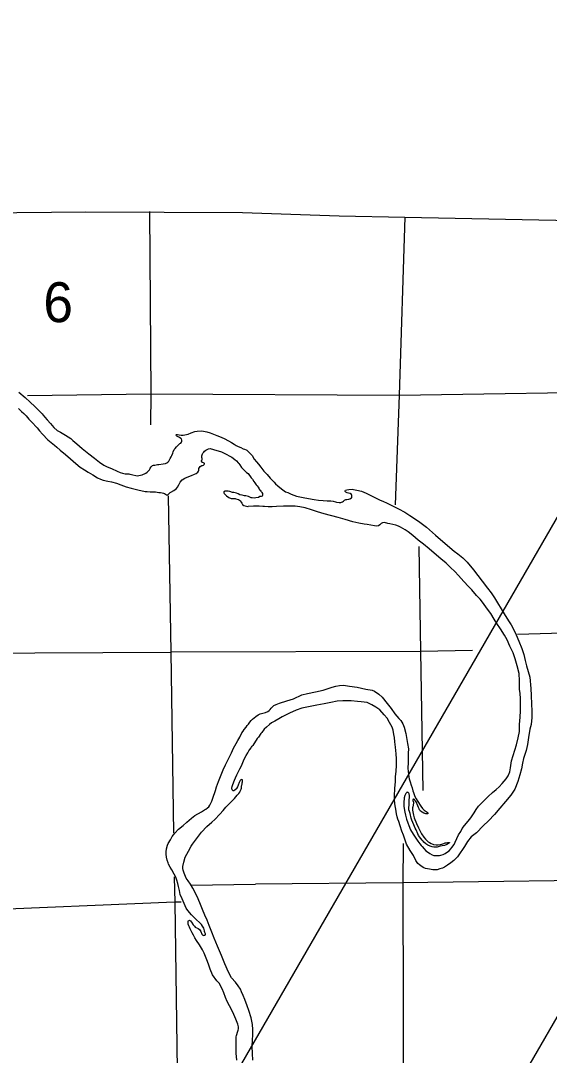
# Model space of a CAD drawing. Extents: x 369523 to 838377, y 495025 to 936819.
# Drawn here: x 640816 to 652011, y 647242 to 669161 of the extents above; entities that cross this region are included whole.
import ezdxf

# ---------------------------------------------------------------- set-up
doc = ezdxf.new("R2010")
doc.units = 0
for name, color, linetype in [('21', 7, 'Continuous'), ('Level 10', 7, 'Continuous'), ('Level 22', 7, 'Continuous'), ('Level 6', 7, 'Continuous')]:
    doc.layers.add(name, color=color, linetype=linetype)

msp = doc.modelspace()

# ---------------------------------------------------------------- linework, layer by layer
at = {"layer": '21'}
for p, q in [((715348, 757482), (625588, 602013)), ((623656, 609226), (708796, 756692))]:
    msp.add_line(p, q, dxfattribs=at)
at = {"layer": 'Level 10'}
for points in [[(640778, 661293), (640908, 661177), (641014, 661081), (641119, 660989), (641209, 660897), (641270, 660834), (641295, 660804), (641329, 660763), (641378, 660702), (641446, 660625), (641480, 660584), (641517, 660544), (641590, 660482), (641657, 660441), (641764, 660379), (641875, 660311), (641920, 660270), (642003, 660195), (642119, 660096), (642258, 659982), (642382, 659892), (642483, 659808), (642578, 659746), (642651, 659711), (642737, 659673), (642858, 659615), (642925, 659591), (642971, 659575), (643027, 659563), (643069, 659559), (643103, 659560), (643131, 659555), (643163, 659545), (643193, 659536), (643252, 659523), (643280, 659517), (643321, 659522), (643389, 659541), (643466, 659577), (643496, 659598), (643525, 659626), (643543, 659643), (643551, 659661), (643558, 659681), (643580, 659707), (643597, 659722), (643609, 659734), (643631, 659742), (643657, 659747), (643711, 659756), (643744, 659759), (643832, 659774), (643884, 659783), (643908, 659792), (643931, 659808), (643953, 659827), (643970, 659855), (643984, 659887), (644001, 659920), (644017, 659952), (644036, 660001), (644045, 660025), (644068, 660073), (644088, 660100), (644117, 660134), (644137, 660157), (644166, 660179), (644190, 660200), (644205, 660212), (644221, 660230), (644227, 660255), (644226, 660275), (644220, 660300), (644208, 660310), (644183, 660330), (644163, 660335), (644137, 660351), (644125, 660359), (644117, 660367), (644112, 660379), (644112, 660381), (644110, 660388), (644114, 660391), (644122, 660393), (644140, 660395), (644172, 660386), (644212, 660382), (644258, 660381), (644362, 660399), (644427, 660429), (644502, 660458), (644552, 660467), (644652, 660469), (644758, 660451), (644829, 660428), (644899, 660400), (644973, 660371), (645024, 660352), (645124, 660306)], [(640767, 660942), (640832, 660882), (640881, 660836), (640931, 660787), (640992, 660722), (641044, 660659), (641166, 660536), (641215, 660472), (641276, 660400), (641390, 660282), (641532, 660168), (641583, 660129), (641654, 660064), (641765, 659971), (641873, 659875), (641983, 659781), (642074, 659704), (642169, 659644), (642246, 659595), (642343, 659539), (642446, 659475), (642506, 659446), (642566, 659427), (642665, 659405), (642741, 659393), (642843, 659365), (642938, 659328), (643050, 659287), (643159, 659255), (643299, 659219), (643453, 659188), (643495, 659183), (643559, 659180), (643623, 659180), (643673, 659177), (643743, 659168), (643777, 659167), (643809, 659159), (643838, 659150), (643860, 659144), (643882, 659129), (643900, 659117), (643932, 659114), (643948, 659128), (643973, 659158), (643979, 659162), (643995, 659173), (644058, 659208), (644119, 659253), (644139, 659278), (644164, 659326), (644191, 659383), (644234, 659430), (644291, 659469), (644376, 659505), (644432, 659524), (644497, 659551), (644535, 659568), (644566, 659594), (644580, 659617), (644586, 659635), (644589, 659671), (644600, 659697), (644620, 659718), (644654, 659734), (644668, 659739), (644687, 659747), (644697, 659751), (644705, 659761), (644711, 659771), (644711, 659777), (644703, 659787), (644699, 659789), (644689, 659793), (644676, 659799), (644658, 659804), (644652, 659810), (644644, 659830), (644648, 659844), (644657, 659860), (644663, 659875), (644661, 659883), (644659, 659897), (644655, 659900), (644650, 659912), (644650, 659924), (644650, 659944), (644665, 659981), (644677, 659997), (644692, 660021), (644710, 660040), (644739, 660060), (644763, 660075)], [(645124, 660306), (645219, 660258), (645278, 660221), (645336, 660186), (645377, 660163), (645425, 660138), (645477, 660117), (645530, 660092), (645558, 660080), (645588, 660067), (645608, 660059)], [(644763, 660075), (644791, 660091), (644831, 660096), (644899, 660075), (645070, 660029), (645183, 659967), (645229, 659940), (645291, 659915), (645354, 659866), (645389, 659833), (645425, 659797), (645436, 659781), (645460, 659748), (645493, 659698), (645524, 659663), (645562, 659624), (645583, 659602), (645601, 659588), (645631, 659571)], [(645608, 660059), (645719, 659947), (645763, 659874), (645810, 659817), (645855, 659764), (645901, 659703), (645965, 659620), (646034, 659546), (646102, 659467), (646123, 659447), (646182, 659381), (646213, 659349), (646264, 659303), (646337, 659246), (646421, 659182), (646471, 659165), (646544, 659129), (646658, 659090), (646795, 659057), (646909, 659037), (647032, 659014), (647126, 659001), (647220, 658995), (647310, 658991), (647382, 658987), (647432, 658980), (647480, 658969), (647506, 658961), (647561, 658955), (647567, 658953), (647597, 658954), (647610, 658958), (647628, 658966), (647650, 658985), (647675, 659004), (647687, 659010), (647703, 659014), (647723, 659017), (647763, 659022), (647788, 659032), (647820, 659051), (647828, 659061), (647829, 659095), (647829, 659103), (647820, 659121), (647796, 659141), (647756, 659154), (647727, 659161), (647701, 659172), (647689, 659184), (647687, 659198), (647698, 659212), (647726, 659221), (647768, 659230), (647838, 659234), (647862, 659226), (647938, 659214), (648034, 659194), (648133, 659151), (648285, 659072), (648416, 659009), (648497, 658973), (648562, 658944), (648675, 658893), (648818, 658820), (648952, 658745), (649059, 658680), (649238, 658556), (649411, 658430), (649603, 658258), (649756, 658125), (649994, 657925), (650077, 657863), (650177, 657781), (650273, 657687), (650403, 657530), (650590, 657290), (650704, 657136), (650780, 657040), (650850, 656935), (651054, 656598), (651144, 656448), (651202, 656363), (651264, 656242), (651307, 656149), (651366, 656018), (651429, 655859), (651474, 655732), (651503, 655605), (651530, 655491), (651600, 655253), (651621, 655015), (651629, 654865), (651637, 654678), (651638, 654542), (651638, 654400), (651625, 654248), (651598, 654151), (651574, 653972), (651551, 653823), (651522, 653700)], [(645631, 659571), (645694, 659477), (645723, 659446), (645756, 659401), (645777, 659369), (645806, 659330), (645816, 659316), (645826, 659304), (645845, 659281), (645864, 659243), (645876, 659225), (645890, 659214), (645905, 659194), (645917, 659178), (645925, 659168), (645938, 659147), (645938, 659137), (645937, 659115), (645939, 659105), (645929, 659088), (645910, 659078), (645884, 659077), (645850, 659056), (645798, 659049), (645766, 659046), (645720, 659049), (645694, 659055), (645638, 659081)], [(645638, 659081), (645586, 659094), (645556, 659097), (645510, 659106), (645460, 659119), (645424, 659134), (645387, 659150), (645359, 659157), (645329, 659163), (645301, 659168), (645245, 659183), (645207, 659190), (645183, 659194), (645157, 659195), (645141, 659193), (645133, 659189), (645125, 659185), (645119, 659181), (645119, 659169), (645118, 659157), (645126, 659141), (645152, 659119), (645177, 659098), (645223, 659060), (645272, 659041), (645296, 659038), (645312, 659036), (645356, 659037), (645372, 659033), (645404, 659026), (645428, 659018), (645432, 659016), (645448, 659005), (645464, 658991), (645485, 658957), (645499, 658938), (645514, 658914), (645540, 658888), (645570, 658881), (645600, 658874), (645630, 658868), (645636, 658870)], [(647685, 658595), (647540, 658638), (647243, 658715), (647102, 658758), (646973, 658801), (646840, 658837), (646730, 658863), (646626, 658874), (646566, 658877), (646486, 658873), (646382, 658875), (646236, 658869), (646140, 658863), (646059, 658861), (645981, 658865), (645943, 658866), (645870, 658873), (645747, 658874), (645636, 658870)], [(649297, 651688), (649317, 651663), (649358, 651614), (649397, 651574), (649430, 651551), (649481, 651516), (649527, 651489), (649563, 651478), (649605, 651473), (649641, 651474), (649689, 651473), (649717, 651480), (649765, 651499), (649806, 651520), (649857, 651551), (649889, 651574), (649928, 651617), (649949, 651646), (649994, 651705), (650020, 651758), (650052, 651838), (650086, 651915), (650135, 651983), (650169, 652048), (650214, 652109), (650293, 652199), (650348, 652272), (650421, 652380), (650459, 652451), (650514, 652520), (650582, 652592), (650718, 652726), (650810, 652808), (650885, 652870), (650949, 652931), (651014, 652999), (651095, 653097), (651138, 653160), (651178, 653247), (651192, 653332), (651214, 653483), (651283, 653705), (651316, 653820), (651350, 653965), (651377, 654103), (651383, 654252), (651394, 654406), (651401, 654543), (651400, 654661), (651399, 654791), (651394, 654913), (651380, 654993), (651382, 655175), (651370, 655331), (651330, 655493), (651291, 655638), (651244, 655765), (651178, 655910), (651117, 656042), (651059, 656145), (650980, 656279), (650901, 656388), (650845, 656483), (650771, 656601), (650682, 656723), (650618, 656814), (650546, 656902), (650466, 656986), (650367, 657100), (650302, 657173), (650203, 657279), (650090, 657404), (650008, 657488), (649920, 657576), (649826, 657668), (649712, 657762), (649625, 657840), (649468, 657970), (649345, 658074), (649237, 658157), (649123, 658251), (649020, 658334), (648957, 658371), (648857, 658431), (648817, 658450), (648763, 658472), (648632, 658499), (648588, 658508), (648518, 658527), (648482, 658526), (648450, 658507), (648419, 658480), (648391, 658462), (648358, 658451), (648309, 658456), (648233, 658474), (648153, 658490), (648091, 658493), (647976, 658518), (647848, 658547), (647685, 658595)], [(645722, 654365), (645794, 654418), (645849, 654457), (645887, 654474), (645917, 654483), (645946, 654489), (645998, 654505), (646051, 654528), (646081, 654545), (646102, 654571), (646120, 654596), (646143, 654618), (646166, 654641), (646180, 654653), (646224, 654672), (646295, 654700), (646454, 654748), (646596, 654795), (646772, 654876), (646887, 654910), (647060, 654942), (647221, 654980), (647306, 655008), (647410, 655041), (647489, 655061), (647566, 655077), (647650, 655081), (647779, 655064), (647941, 655038), (648126, 655002), (648260, 654975), (648309, 654954), (648404, 654890), (648469, 654826), (648576, 654698), (648661, 654590), (648743, 654474), (648824, 654379), (648867, 654334), (648908, 654267), (648938, 654194), (648975, 654058), (648989, 653975), (649008, 653849), (649029, 653733), (649025, 653643), (649022, 653595), (649022, 653525), (649022, 653441), (649014, 653334), (649024, 653244), (649031, 653202), (649037, 653136), (649042, 653100), (649061, 653035), (649083, 652965), (649104, 652906), (649124, 652846), (649134, 652808), (649147, 652766), (649166, 652725), (649191, 652677), (649216, 652640), (649239, 652600), (649264, 652563), (649287, 652521), (649326, 652470), (649349, 652449), (649363, 652437), (649404, 652408), (649424, 652396), (649434, 652387), (649440, 652379), (649442, 652369), (649441, 652361), (649429, 652354), (649425, 652354), (649393, 652354), (649354, 652373), (649316, 652390), (649284, 652415), (649275, 652425), (649261, 652443), (649252, 652464), (649240, 652492), (649229, 652526), (649212, 652562), (649208, 652578), (649203, 652594), (649193, 652613), (649185, 652621), (649166, 652645), (649154, 652658), (649146, 652664), (649140, 652668), (649132, 652668), (649124, 652664), (649122, 652652), (649124, 652636), (649127, 652628), (649134, 652592)], [(651522, 653700), (651466, 653533), (651443, 653428), (651422, 653309), (651389, 653186), (651342, 653041), (651278, 652883), (651193, 652753), (651085, 652616), (650966, 652481), (650847, 652346), (650721, 652211), (650613, 652100), (650467, 651958), (650359, 651870), (650280, 651768), (650216, 651666), (650172, 651599), (650124, 651528), (650064, 651448), (649988, 651366), (649927, 651321), (649856, 651267), (649793, 651225), (649746, 651206), (649692, 651189), (649637, 651174), (649593, 651170), (649545, 651171), (649473, 651184), (649392, 651200), (649352, 651217), (649322, 651232), (649263, 651275), (649226, 651306), (649182, 651369), (649132, 651474), (649062, 651581), (648988, 651717), (648950, 651824), (648922, 651906), (648890, 651991), (648853, 652104), (648823, 652196), (648802, 652245), (648789, 652291), (648773, 652361), (648761, 652453), (648752, 652493), (648743, 652567), (648730, 652662), (648732, 652741), (648741, 652897), (648751, 653040), (648755, 653140), (648766, 653262), (648773, 653383), (648776, 653523), (648767, 653629), (648754, 653767), (648739, 653885), (648731, 653975), (648722, 654040), (648706, 654130), (648684, 654192), (648630, 654295), (648574, 654383), (648512, 654458), (648420, 654558), (648334, 654616), (648251, 654668), (648154, 654716), (648026, 654729), (647948, 654735), (647812, 654748), (647636, 654752), (647520, 654745), (647381, 654714), (647244, 654688), (647087, 654659), (646944, 654631), (646771, 654593), (646652, 654556), (646506, 654489), (646427, 654447), (646354, 654411), (646285, 654371), (646196, 654323), (646131, 654285), (646084, 654248), (646019, 654197), (645970, 654149), (645922, 654082), (645901, 654056), (645850, 653982), (645825, 653954), (645734, 653808)], [(644676, 649787), (644690, 649783), (644702, 649785), (644714, 649788), (644720, 649788), (644726, 649792), (644730, 649804), (644727, 649816), (644723, 649832), (644717, 649846), (644711, 649868), (644708, 649876), (644700, 649909), (644693, 649935), (644666, 649981), (644642, 650014), (644615, 650042), (644526, 650126), (644473, 650177), (644434, 650221), (644355, 650313), (644324, 650357), (644276, 650456), (644236, 650559), (644197, 650651), (644177, 650732), (644158, 650818), (644143, 650882), (644125, 650952), (644102, 651015), (644069, 651079), (644015, 651170), (643980, 651225), (643949, 651289), (643937, 651316), (643918, 651374), (643905, 651436), (643895, 651504), (643896, 651556), (643905, 651614), (643926, 651695), (643937, 651729), (643986, 651808), (644026, 651877), (644079, 651946), (644161, 652030), (644258, 652108), (644336, 652183), (644432, 652267), (644503, 652319), (644646, 652403), (644707, 652439), (644737, 652455), (644772, 652482), (644798, 652504), (644825, 652543), (644863, 652624), (644888, 652688), (644939, 652850), (644963, 652930), (645003, 653041), (645061, 653184), (645103, 653287), (645154, 653398), (645208, 653512), (645280, 653649), (645326, 653752), (645378, 653845), (645417, 653910), (645455, 653981), (645503, 654074), (645527, 654106), (645552, 654143), (645593, 654196), (645614, 654228), (645638, 654257), (645669, 654299), (645698, 654334), (645722, 654365)], [(645435, 652789), (645457, 652818), (645464, 652840), (645484, 652878), (645489, 652902), (645496, 652939), (645502, 652971), (645506, 652989), (645509, 653017), (645511, 653033), (645516, 653065), (645514, 653075), (645506, 653079), (645494, 653083), (645480, 653080), (645466, 653066), (645445, 653020), (645424, 652963), (645407, 652927), (645389, 652896), (645386, 652888), (645360, 652866), (645352, 652862), (645328, 652847), (645314, 652847), (645306, 652855), (645296, 652869), (645288, 652898), (645295, 652935), (645306, 652977), (645342, 653068), (645367, 653120), (645396, 653181), (645425, 653241), (645460, 653312), (645483, 653361), (645508, 653413), (645538, 653482), (645559, 653528), (645594, 653593), (645594, 653595), (645625, 653650), (645650, 653694), (645672, 653721), (645697, 653757), (645705, 653770), (645718, 653790), (645734, 653808)], [(645736, 647138), (645723, 647282), (645716, 647428), (645726, 647569), (645734, 647667), (645732, 647787), (645724, 647893), (645697, 648033), (645648, 648188), (645612, 648291), (645560, 648424), (645529, 648506), (645495, 648589), (645470, 648641), (645423, 648712), (645362, 648789), (645282, 648886), (645220, 649004), (645141, 649181), (645070, 649356), (644986, 649555), (644913, 649723), (644863, 649849), (644810, 649992), (644764, 650103), (644718, 650212), (644670, 650333), (644624, 650439), (644572, 650558), (644524, 650665), (644462, 650780), (644414, 650865), (644361, 650938), (644320, 650993), (644304, 651027), (644276, 651097), (644259, 651164), (644252, 651200), (644252, 651244), (644274, 651335), (644302, 651440), (644369, 651569), (644425, 651676), (644453, 651713), (644540, 651831), (644648, 651969), (644757, 652087), (644861, 652181), (644928, 652239), (645036, 652353), (645104, 652428), (645163, 652502), (645230, 652567), (645292, 652634), (645347, 652685), (645404, 652754), (645435, 652789)], [(649134, 652592), (649131, 652544), (649122, 652505), (649116, 652483), (649114, 652469), (649115, 652433), (649122, 652397), (649132, 652331), (649149, 652274), (649198, 652153), (649242, 652060), (649278, 651988), (649307, 651931), (649355, 651860), (649388, 651819), (649426, 651782), (649447, 651766), (649477, 651747), (649512, 651729), (649544, 651716), (649560, 651711), (649618, 651702), (649658, 651701), (649698, 651706), (649734, 651715), (649759, 651723), (649775, 651730), (649807, 651740), (649825, 651745), (649857, 651750), (649869, 651752), (649883, 651752), (649891, 651752), (649897, 651751), (649901, 651745), (649885, 651734), (649875, 651728), (649840, 651707), (649794, 651690), (649744, 651679), (649697, 651672), (649639, 651652), (649605, 651652), (649565, 651653), (649527, 651660), (649485, 651673), (649438, 651696), (649396, 651719), (649353, 651756), (649337, 651775), (649320, 651803), (649291, 651836), (649244, 651895), (649225, 651935), (649191, 652018), (649170, 652056), (649141, 652123), (649119, 652173), (649102, 652223), (649087, 652264), (649061, 652362), (649048, 652406), (649039, 652443), (649039, 652463), (649038, 652493), (649041, 652538), (649044, 652578), (649043, 652630), (649046, 652652), (649047, 652704), (649048, 652730), (649048, 652750), (649048, 652754), (649045, 652768), (649043, 652776), (649041, 652782), (649039, 652792), (649031, 652800), (649023, 652806), (649016, 652811), (649006, 652813), (649000, 652815), (648989, 652809), (648985, 652805), (648973, 652786), (648950, 652746), (648935, 652699), (648930, 652593), (648928, 652519), (648935, 652469), (648952, 652393), (648964, 652331), (648984, 652246), (649012, 652166), (649037, 652107), (649073, 652022), (649131, 651925), (649183, 651844), (649227, 651781), (649270, 651724), (649297, 651688)], [(645392, 647136), (645381, 647286), (645383, 647422), (645383, 647514), (645382, 647592), (645383, 647630), (645388, 647662), (645394, 647686), (645409, 647731), (645417, 647751), (645424, 647777), (645430, 647805), (645427, 647845), (645412, 647899), (645374, 648010), (645332, 648104), (645289, 648199), (645239, 648288), (645189, 648385), (645154, 648465), (645116, 648562), (645085, 648649), (645022, 648768), (644970, 648821), (644881, 648950), (644829, 649067), (644791, 649172), (644756, 649266), (644699, 649405), (644666, 649478), (644602, 649581), (644540, 649676), (644505, 649733), (644478, 649787), (644449, 649837), (644420, 649892), (644408, 649920), (644393, 649954), (644375, 649987), (644366, 650019), (644364, 650055), (644361, 650069), (644361, 650083), (644367, 650097), (644375, 650101), (644391, 650104), (644409, 650094), (644433, 650060), (644470, 650009), (644495, 649976), (644509, 649960), (644523, 649950), (644563, 649935), (644574, 649925), (644600, 649904), (644618, 649888), (644633, 649862), (644641, 649844), (644647, 649828), (644654, 649808), (644660, 649801), (644676, 649787)]]:
    msp.add_lwpolyline(points, dxfattribs=at)
at = {"layer": 'Level 22'}
for points in [[(643541, 665117), (643571, 661257), (643563, 660596)], [(648950, 665000), (648831, 661228), (648750, 658905)], [(643571, 661257), (648831, 661228), (654221, 661314), (659594, 661394), (661286, 661400)], [(640961, 661218), (643571, 661257)], [(643938, 659096), (643998, 655781), (644055, 651953)], [(649251, 658019), (649283, 655797), (649335, 652851)], [(651340, 656166), (654217, 656246), (659543, 656387), (660985, 656367)], [(613081, 656010), (618578, 655993), (623784, 655875), (629065, 655755), (634462, 655732), (639666, 655759), (643998, 655781)], [(650386, 655815), (649283, 655797), (643998, 655781)], [(648914, 651729), (648906, 650890), (648925, 645618)], [(644064, 651022), (644080, 650476), (644154, 645416)], [(660347, 651079), (659579, 651095), (654262, 650965), (648902, 650894), (645789, 650864)], [(644423, 650845), (645789, 650864)], [(644216, 650487), (644074, 650484), (639698, 650301)]]:
    msp.add_lwpolyline(points, dxfattribs=at)
at = {"layer": 'Level 6'}
for points in [[(640003, 665090), (642199, 665109), (645512, 665099)], [(640003, 665090), (642199, 665109), (645512, 665099)], [(645512, 665099), (647563, 665029), (648950, 665000), (653566, 664909), (654216, 664888), (657497, 664864)]]:
    msp.add_lwpolyline(points, dxfattribs=at)

# ---------------------------------------------------------------- texts
at = {"layer": 'Level 22'}
msp.add_text('6', height=845, dxfattribs=at).set_placement((641296, 662774))

doc.saveas('drawing.dxf')
